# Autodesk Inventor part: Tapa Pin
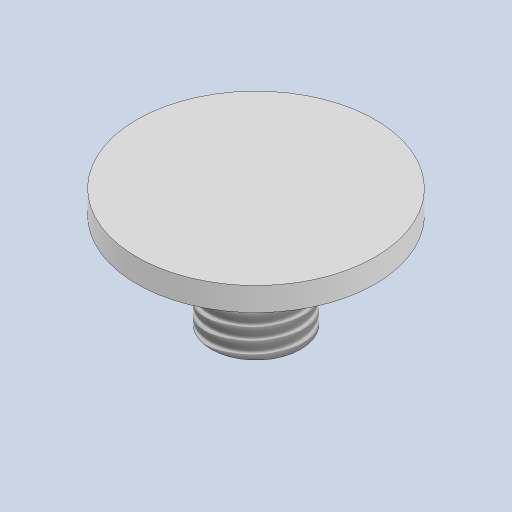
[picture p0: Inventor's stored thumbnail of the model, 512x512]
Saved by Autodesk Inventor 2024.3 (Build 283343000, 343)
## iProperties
Created: 2025-10
Part Number: Tapa Pin
Material: Genérico
Document SubType Name: Modeling
Designer: Asus
Density: 1 g/cm^3
Appearance: Valor por defecto
Author: Asus
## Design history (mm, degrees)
sketch "Boceto1"
  geometry: C1 r 25.4 at (0, 0); 1 further point
  constraints: 1 centre point, 1 coincident
  dimensions: "d0" = 50.8 diameter of C1
extrude "Extrusión1" new body sketch "Boceto1" distance "d1" = 5; taper "d2" = 0 deg
sketch "Boceto2"
  geometry: C1 r 9.525 at (0, 0); 1 further point
  constraints: 1 centre point, 1 coincident
  dimensions: "d3" = 19.05 diameter of C1
extrude "Extrusión2" join sketch "Boceto2" distance "d4" = 20; taper "d5" = 0 deg
feature "Rosca1" dims "d13" = 100, "d14" = 0
node "Sólido1"
